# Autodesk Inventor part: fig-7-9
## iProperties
Shininess: 77.0
Angle Display Precision: 2
Document Length Units: 11269
Document Angle Units: 11279
Document Time Units: 11290
Document Mass Units: 11283
Document Length Units Precision: 3
Document Angle Units Precision: 2
Created: 2001-12
Part Number: fig-7-9
Document SubType Name: Modeling
Designer: CADSoft
Density: 1 g/cm^3
Density: 0.0
Volumn: 0.0
Area: 0.0
PropertySet Name: Model Information
Control State: 0
Master: False
Checked Out: False
Author: CADSoft
